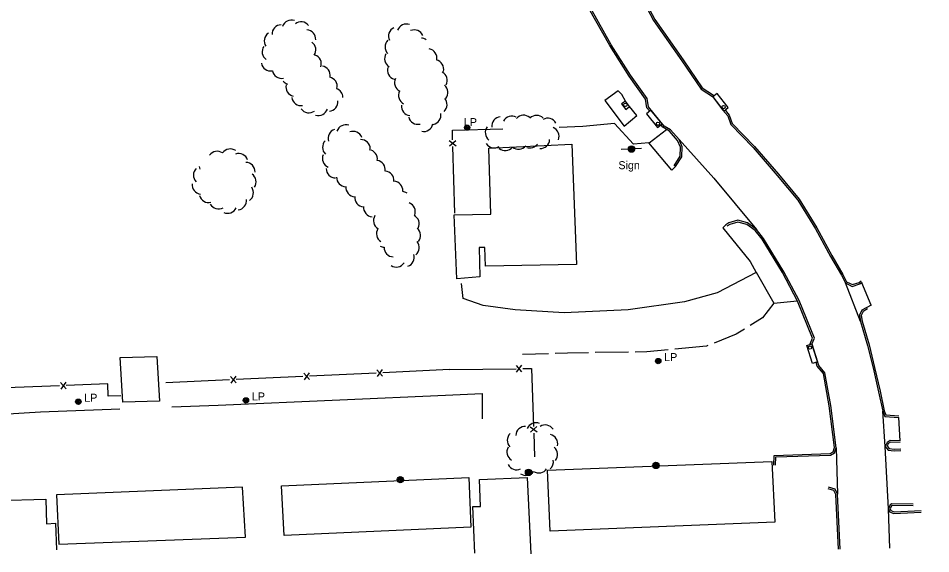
# Model space of a CAD drawing. Extents: x 2402803 to 2427059, y 6985292 to 6997652.
# Drawn here: x 2406106 to 2406653, y 6990711 to 6991032 of the extents above; entities that cross this region are included whole.
import ezdxf

# ---------------------------------------------------------------- set-up
doc = ezdxf.new("R2010")
doc.units = 0
for name, color, linetype in [('p_drainage conc drain', 7, 'Continuous'), ('p_dtm sidewalk', 7, 'Continuous'), ('p_road - paved curb', 7, 'Continuous'), ('p_road bridge end', 7, 'Continuous'), ('p_road dirt road', 7, 'Continuous'), ('p_structure building', 7, 'Continuous'), ('p_structure fence', 7, 'Continuous'), ('p_structure general', 7, 'Continuous'), ('p_structure sign', 7, 'Continuous'), ('p_utility manhole', 7, 'Continuous'), ('p_veg woods', 7, 'Continuous')]:
    doc.layers.add(name, color=color, linetype=linetype)

msp = doc.modelspace()

# ---------------------------------------------------------------- linework, layer by layer
at = {"layer": 'p_drainage conc drain'}
msp.add_lwpolyline([(2406470.12, 6990982.64), (2406467.75, 6990986.64), (2406465.58, 6990988.81), (2406457.6, 6990982.96), (2406469.2, 6990967.61), (2406476.89, 6990973.94), (2406472.53, 6990979.37)], dxfattribs=at)
at = {"layer": 'p_dtm sidewalk'}
for points in [[(2406484.14, 6990957.47), (2406494.7, 6990965.58)], [(2406548.34, 6990880), (2406559.06, 6990861.41), (2406573.07, 6990862.77)]]:
    msp.add_lwpolyline(points, dxfattribs=at)
at = {"layer": 'p_road - paved curb'}
for points in [[(2406708.9, 6991166.9), (2406647.83, 6991166.44), (2406582.25, 6991166.09), (2406531.73, 6991165.73), (2406487.36, 6991165.29), (2406459.5, 6991165.37), (2406452.36, 6991163.12), (2406447.05, 6991158.65), (2406443.39, 6991153.84), (2406440.89, 6991146.51), (2406441.68, 6991141.43), (2406444.32, 6991132.11), (2406449.65, 6991114.89), (2406456.34, 6991094.62), (2406466.16, 6991073.25), (2406480.07, 6991045.94), (2406487.68, 6991031.47), (2406504.65, 6991007.34), (2406516.03, 6990990.53), (2406522.84, 6990986.1), (2406523.08, 6990985.78)], [(2406484.48, 6990976.73), (2406482.92, 6990978.65), (2406482, 6990983.74), (2406472.17, 6990997.55), (2406460.68, 6991015.91), (2406448.13, 6991038.09), (2406436.79, 6991060.23), (2406427.45, 6991082.91), (2406418.15, 6991108.07), (2406409.15, 6991138.19), (2406403.36, 6991163.29)], [(2406500.1, 6990943.3), (2406503.79, 6990949.22), (2406504.04, 6990955.11), (2406502.14, 6990959.6), (2406497.11, 6990965.32), (2406493.14, 6990967.66), (2406483.86, 6990979.08), (2406482.94, 6990984.14), (2406473, 6990998.11), (2406461.54, 6991016.42), (2406449.01, 6991038.56), (2406437.7, 6991060.65), (2406428.38, 6991083.27), (2406419.1, 6991108.39), (2406410.12, 6991138.45), (2406404.33, 6991163.52)], [(2406479.18, 6991045.48), (2406486.82, 6991030.95), (2406503.83, 6991006.77), (2406515.32, 6990989.8), (2406522.15, 6990985.35), (2406528.43, 6990977.21), (2406531.41, 6990973.69), (2406533.13, 6990968.64), (2406546.64, 6990954.69), (2406561.01, 6990938.03), (2406573.31, 6990923.17), (2406583.97, 6990906.08), (2406592.97, 6990889.44), (2406599.51, 6990878.21), (2406601.92, 6990873.54), (2406606.04, 6990871.43), (2406610.59, 6990872.99), (2406611.99, 6990873.96)], [(2406529.95, 6990976.96), (2406532.3, 6990974.19), (2406534, 6990969.17), (2406547.38, 6990955.36), (2406561.77, 6990938.68), (2406574.12, 6990923.76), (2406584.83, 6990906.58), (2406593.84, 6990889.93), (2406600.39, 6990878.69), (2406602.66, 6990874.28), (2406606.12, 6990872.51), (2406610.13, 6990873.89), (2406611.42, 6990874.78)], [(2406500.1, 6990943.3), (2406497.91, 6990941.18), (2406484.09, 6990957.53), (2406474.87, 6990956.79), (2406463.52, 6990969.26), (2406444.5, 6990967.33), (2406430.32, 6990966.76)], [(2406499.25, 6990943.83), (2406502.8, 6990949.53), (2406503.03, 6990954.93), (2406501.28, 6990959.06), (2406496.46, 6990964.54), (2406492.48, 6990966.89), (2406491.49, 6990968.11)], [(2406502.14, 6990959.6), (2406523.11, 6990936.3), (2406548.54, 6990905.67)], [(2406530.29, 6990908.38), (2406528.41, 6990906.65), (2406544.8, 6990886.3), (2406548.48, 6990879.75), (2406524.95, 6990867.65), (2406505.5, 6990862.2), (2406471.68, 6990857.46), (2406433.28, 6990855.59), (2406403.89, 6990857.36), (2406384.73, 6990859.94), (2406372.64, 6990864.11), (2406371.67, 6990873.14)], [(2406559.94, 6990764.15), (2406560.17, 6990769.16), (2406592.95, 6990770.32), (2406595.31, 6990771.62), (2406596.41, 6990774.67), (2406593.12, 6990799.94), (2406589.64, 6990819.7), (2406585.95, 6990824.07), (2406581.8, 6990836.88), (2406583.32, 6990840.5), (2406574.11, 6990862.95), (2406564.99, 6990880.21), (2406552.87, 6990900.27), (2406548.54, 6990905.67), (2406543.18, 6990909.56), (2406537.49, 6990911.09), (2406532.09, 6990909.54), (2406530.29, 6990908.32)], [(2406580.81, 6990836.68), (2406580.73, 6990836.92), (2406582.24, 6990840.5), (2406573.2, 6990862.53), (2406564.12, 6990879.72), (2406552.05, 6990899.7), (2406547.84, 6990904.94), (2406542.74, 6990908.64), (2406537.5, 6990910.05), (2406532.52, 6990908.62), (2406530.85, 6990907.49)], [(2406610.95, 6990850.33), (2406601.92, 6990873.54)], [(2406617.32, 6990860.27), (2406611.81, 6990873.59)], [(2406617.25, 6990860.11), (2406617.32, 6990860.27), (2406611.75, 6990857.11), (2406610.41, 6990854.25), (2406610.95, 6990850.33), (2406615.16, 6990836.07), (2406618.49, 6990822.66), (2406621.71, 6990808.32), (2406624.26, 6990796.61), (2406625.54, 6990793.42), (2406633.94, 6990792.82)], [(2406615.2, 6990857.92), (2406615.2, 6990857.92), (2406612.52, 6990856.4), (2406611.44, 6990854.09), (2406611.93, 6990850.54), (2406616.13, 6990836.33), (2406619.46, 6990822.89), (2406622.69, 6990808.54), (2406625.22, 6990796.9), (2406626.24, 6990794.37), (2406634.01, 6990793.82)], [(2406558.94, 6990764.2), (2406559.21, 6990770.13), (2406592.68, 6990771.31), (2406594.5, 6990772.31), (2406595.39, 6990774.78), (2406592.13, 6990799.79), (2406588.7, 6990819.26), (2406585.06, 6990823.57), (2406584.33, 6990825.81)], [(2406197.99, 6990799.16), (2406225.71, 6990800.19), (2406298.7, 6990803.41), (2406362.04, 6990806.24), (2406384.05, 6990807.17), (2406384.08, 6990791.97)], [(2406043.13, 6990760.46), (2406043.42, 6990781.32), (2406042.97, 6990792.02), (2406063.66, 6990792.89), (2406119.32, 6990796.14), (2406166.75, 6990797.99)], [(2406628.57, 6990714.5), (2406627.67, 6990738.01), (2406625.81, 6990775.48), (2406624.26, 6990796.61)], [(2406634.8, 6990778.91), (2406633.94, 6990792.82)], [(2406634.8, 6990778.91), (2406628.72, 6990778.99), (2406626.86, 6990777.91), (2406625.81, 6990775.48), (2406627.56, 6990773.31), (2406631.11, 6990772.93), (2406635.24, 6990773.07)], [(2406634.79, 6990777.91), (2406628.98, 6990777.99), (2406627.65, 6990777.21), (2406626.97, 6990775.64), (2406628.08, 6990774.26), (2406631.15, 6990773.93), (2406635.21, 6990774.07)], [(2406596.41, 6990774.67), (2406597.26, 6990746.95)], [(2406597.69, 6990713.83), (2406596.27, 6990746.67), (2406595.01, 6990748.96), (2406591.48, 6990750.11)], [(2406598.69, 6990713.87), (2406597.26, 6990746.95), (2406595.69, 6990749.79), (2406591.79, 6990751.06)], [(2406642.61, 6990740.84), (2406629.83, 6990741.14), (2406628.75, 6990740.44), (2406627.67, 6990738.01), (2406628.41, 6990736.23), (2406631, 6990735.31), (2406647.39, 6990736)], [(2406642.59, 6990739.84), (2406630.11, 6990740.13), (2406629.54, 6990739.76), (2406628.76, 6990738), (2406629.16, 6990737.02), (2406631.15, 6990736.32), (2406647.35, 6990737)]]:
    msp.add_lwpolyline(points, dxfattribs=at)
at = {"layer": 'p_road bridge end'}
for points in [[(2406522.42, 6990985.16), (2406529.06, 6990976.64), (2406531.65, 6990978.66), (2406525.01, 6990987.18)], [(2406472.53, 6990979.37), (2406470.12, 6990982.64), (2406467.74, 6990980.88), (2406470.15, 6990977.61)], [(2406491.93, 6990968.98), (2406485.3, 6990977.16), (2406482.68, 6990975.04), (2406489.31, 6990966.86)], [(2406581.71, 6990836.94), (2406585.16, 6990826.17), (2406582.21, 6990825.22), (2406578.76, 6990835.99)]]:
    msp.add_lwpolyline(points, close=True, dxfattribs=at)
at = {"layer": 'p_road dirt road'}
for p, q in [((2406423.77, 6990831.1), (2406408.2, 6990830.59)), ((2406471.75, 6990832.03), (2406451.76, 6990831.72))]:
    msp.add_line(p, q, dxfattribs=at)
for points in [[(2406559.06, 6990861.41), (2406552.17, 6990852.54), (2406544.72, 6990847.92)], [(2406541.32, 6990845.82), (2406536.36, 6990842.74), (2406523.22, 6990837.48)], [(2406519.51, 6990835.99), (2406518.66, 6990835.65), (2406499.67, 6990833.82)], [(2406447.76, 6990831.66), (2406435.2, 6990831.47), (2406427.77, 6990831.23)], [(2406495.69, 6990833.43), (2406482.92, 6990832.2), (2406475.75, 6990832.09)]]:
    msp.add_lwpolyline(points, dxfattribs=at)
at = {"layer": 'p_structure building'}
for points in [[(2406368.82, 6990876.07), (2406367.28, 6990914.42), (2406389.27, 6990914.83), (2406388.06, 6990954.38), (2406437.89, 6990956.71), (2406440.58, 6990884.59), (2406386.15, 6990883.5), (2406385.77, 6990894.83), (2406382.28, 6990894.75), (2406382.73, 6990877.11)], [(2406167.05, 6990828.73), (2406189.03, 6990829.34), (2406190.64, 6990802.68), (2406168.5, 6990802.04)], [(2406423.22, 6990761.18), (2406557.82, 6990766.48), (2406559.61, 6990729.97), (2406424.84, 6990724.7)], [(2406377.24, 6990727), (2406265.28, 6990722.11), (2406263.78, 6990751.9), (2406376.01, 6990756.82)], [(2406240.42, 6990751.15), (2406128.78, 6990746.37), (2406130.14, 6990716.87), (2406242.07, 6990721.15)]]:
    msp.add_lwpolyline(points, close=True, dxfattribs=at)
for points in [[(2406379.73, 6990711.39), (2406378.53, 6990739.43), (2406383.01, 6990739.47), (2406382.44, 6990755.59), (2406411.03, 6990756.77), (2406413.33, 6990711.12)], [(2406094.55, 6990713.36), (2406093.27, 6990743.04), (2406122.39, 6990743.76), (2406122.74, 6990729.06), (2406128.23, 6990729.42), (2406128.78, 6990713.45)]]:
    msp.add_lwpolyline(points, dxfattribs=at)
at = {"layer": 'p_structure fence'}
for p, q in [((2406368.46, 6990955.6), (2406364.37, 6990958.68)), ((2406368.37, 6990958.8), (2406364.46, 6990955.48)), ((2406367.66, 6990915.36), (2406366.5, 6990955.34)), ((2406277.05, 6990819.45), (2406280.44, 6990815.6)), ((2406280.25, 6990819.6), (2406277.24, 6990815.45)), ((2406320.49, 6990819.51), (2406280.54, 6990817.64)), ((2406320.99, 6990821.5), (2406324.38, 6990817.65)), ((2406324.19, 6990821.65), (2406321.18, 6990817.51)), ((2406364.43, 6990821.56), (2406324.48, 6990819.69)), ((2406364.43, 6990821.56), (2406404.43, 6990822.09)), ((2406407.85, 6990820.16), (2406404.6, 6990824.12)), ((2406404.65, 6990820.12), (2406407.8, 6990824.16)), ((2406131.23, 6990813.91), (2406134.59, 6990810.04)), ((2406134.43, 6990814.04), (2406131.4, 6990809.91)), ((2406232.61, 6990815.4), (2406194.43, 6990813.61)), ((2406233.11, 6990817.39), (2406236.5, 6990813.54)), ((2406236.31, 6990817.54), (2406233.3, 6990813.4)), ((2406276.55, 6990817.45), (2406236.6, 6990815.58)), ((2406130.71, 6990811.91), (2406090.75, 6990810.24)), ((2406412.91, 6990787.22), (2406417.02, 6990784.16)), ((2406413.02, 6990784.02), (2406416.91, 6990787.36)), ((2406415.01, 6990783.49), (2406415.5, 6990769.19))]:
    msp.add_line(p, q, dxfattribs=at)
for points in [[(2406366.38, 6990959.34), (2406366.21, 6990965.2), (2406396.57, 6990965.91)], [(2406408.43, 6990822.14), (2406413.68, 6990822.21), (2406414.87, 6990787.49)], [(2406167.39, 6990805.78), (2406159.86, 6990805.6), (2406159.62, 6990813.12), (2406134.71, 6990812.08)]]:
    msp.add_lwpolyline(points, dxfattribs=at)
at = {"layer": 'p_structure general'}
for centre in [(2406469.97, 6990980.36), (2406528.86, 6990979.03), (2406489.49, 6990969.04), (2406580.6, 6990834.76)]:
    msp.add_circle(centre, 1, dxfattribs=at)
at = {"layer": 'p_structure sign'}
msp.add_line((2406479.68, 6990954.09), (2406467.52, 6990953.53), dxfattribs=at)
for radius in [1.9, 1.44, 0.973, 0.539, 0.192]:
    msp.add_circle((2406473.6, 6990953.81), radius, dxfattribs=at)
at = {"layer": 'p_utility manhole'}
for centre, radius in [((2406375.1, 6990966.68), 1.6), ((2406375.1, 6990966.68), 1.3), ((2406375.1, 6990966.68), 1), ((2406375.1, 6990966.68), 0.539), ((2406375.1, 6990966.68), 0.192), ((2406489.66, 6990826.66), 1.6), ((2406489.66, 6990826.66), 1.3), ((2406489.66, 6990826.66), 1), ((2406489.66, 6990826.66), 0.539), ((2406489.66, 6990826.66), 0.192), ((2406141.91, 6990802.3), 1.6), ((2406141.91, 6990802.3), 1.3), ((2406141.91, 6990802.3), 1), ((2406141.91, 6990802.3), 0.539), ((2406242.45, 6990803.07), 1.6), ((2406242.45, 6990803.07), 1.3), ((2406242.45, 6990803.07), 1), ((2406242.45, 6990803.07), 0.539), ((2406242.45, 6990803.07), 0.192), ((2406141.91, 6990802.3), 0.192), ((2406488.3, 6990764.07), 1.9), ((2406488.3, 6990764.07), 1.44), ((2406488.3, 6990764.07), 0.973), ((2406488.3, 6990764.07), 0.539), ((2406411.88, 6990759.9), 1.9), ((2406411.88, 6990759.9), 1.44), ((2406411.88, 6990759.9), 0.973), ((2406411.88, 6990759.9), 0.539), ((2406411.88, 6990759.9), 0.192), ((2406488.3, 6990764.07), 0.192), ((2406335, 6990755.56), 1.9), ((2406335, 6990755.56), 1.44), ((2406335, 6990755.56), 0.973), ((2406335, 6990755.56), 0.539), ((2406335, 6990755.56), 0.192)]:
    msp.add_circle(centre, radius, dxfattribs=at)
at = {"layer": 'p_veg woods'}
for centre, start, end in [((2406263.75, 6991022.75), 92.9275, 182.9275), ((2406269.74, 6991025.58), 71.7181, 161.7181), ((2406275.53, 6991024.49), 37.8632, 127.8632), ((2406338.63, 6991023.17), 69.7873, 159.7873), ((2406259.03, 6991018.67), 123.7834, 213.7834), ((2406278.64, 6991019.66), 356.6336, 86.6336), ((2406333.53, 6991021.55), 116.3137, 206.3137), ((2406343.33, 6991019.67), 22.933, 112.933), ((2406278.69, 6991013.37), 324.6466, 54.6466), ((2406331.47, 6991015.11), 134.8159, 224.8159), ((2406347.22, 6991014.77), 54.9677, 85.5989), ((2406257.78, 6991012.21), 145.1318, 235.1318), ((2406331.21, 6991008.02), 148.7222, 238.7222), ((2406351.29, 6991008.41), 348.8301, 78.8301), ((2406281.99, 6991004.88), 341.1261, 71.1261), ((2406355.38, 6991001.71), 346.7021, 76.7021), ((2406257.21, 6991006.36), 190.8325, 280.8325), ((2406263.83, 6991001.87), 190.8325, 280.8325), ((2406287.33, 6990998.01), 350.5347, 80.5347), ((2406332.89, 6991001.21), 163.1975, 253.1975), ((2406357.46, 6990995.09), 331.1979, 61.1979), ((2406269.2, 6990998.06), 218.9245, 249.9638), ((2406291.49, 6990991.4), 347.8542, 77.8542), ((2406337.16, 6990993.71), 154.6059, 244.6059), ((2406272.05, 6990991.04), 166.5044, 256.5044), ((2406294.97, 6990984.65), 1.785, 71.8874), ((2406357.94, 6990987.74), 321.3869, 51.3869), ((2406275.5, 6990985.5), 188.3713, 278.3713), ((2406339.61, 6990985.94), 152.4945, 242.4945), ((2406357.38, 6990980.55), 313.1065, 39.9739), ((2406291.95, 6990982.2), 275.144, 5.144), ((2406341.27, 6990979.53), 174.1171, 264.1171), ((2406280.21, 6990981.21), 215.5556, 305.5556), ((2406285.88, 6990979.52), 252.7176, 342.7176), ((2406345.53, 6990974.33), 193.2828, 283.2828), ((2406353.69, 6990974.18), 280.9096, 10.9096), ((2406395.57, 6990967.63), 97.0692, 187.0692), ((2406401.85, 6990967.95), 61.8546, 151.8546), ((2406409.01, 6990968.45), 49.5684, 139.5684), ((2406416.7, 6990968.36), 45.0016, 135.0016), ((2406302.31, 6990962.74), 70.6478, 160.6478), ((2406348.95, 6990970), 258.4254, 348.4254), ((2406391.6, 6990963.73), 142.3145, 232.3145), ((2406423.43, 6990966.66), 29.6859, 119.6859), ((2406297.36, 6990960.3), 108.796, 198.796), ((2406306.69, 6990958.79), 20.8256, 110.8256), ((2406424.54, 6990961.45), 338.4861, 68.4861), ((2406294, 6990954.86), 136.0057, 226.0057), ((2406311.33, 6990953.86), 1.1531, 91.1531), ((2406391.24, 6990960.17), 213.1435, 303.1435), ((2406412.66, 6990960.12), 251.653, 324.1292), ((2406418.91, 6990959.83), 267.2573, 357.2573), ((2406225.18, 6990946.87), 55.0426, 145.0426), ((2406233.05, 6990948.26), 55.0426, 145.0426), ((2406238.08, 6990945.48), 19.3372, 109.3372), ((2406315.61, 6990947.78), 352.5689, 82.5689), ((2406397.87, 6990958.57), 230.7051, 320.7051), ((2406405.83, 6990959.36), 230.7051, 320.7051), ((2406242.27, 6990940.21), 358.39, 88.39), ((2406293.96, 6990948.21), 156.7249, 246.7249), ((2406320.34, 6990941.39), 351.8851, 81.8851), ((2406216.56, 6990938.17), 134.2679, 224.2679), ((2406220.07, 6990943.94), 184.9863, 202.1814), ((2406296.18, 6990942.13), 180.4189, 270.4189), ((2406325.46, 6990935.05), 353.9647, 83.9647), ((2406242.9, 6990934.16), 326.0195, 56.0195), ((2406302.44, 6990936.89), 178.2964, 268.2964), ((2406330.86, 6990928.96), 356.0298, 86.0298), ((2406215.76, 6990932.47), 174.3184, 264.3184), ((2406241.27, 6990927.65), 305.1396, 35.1396), ((2406307.97, 6990930.91), 176.2376, 266.2376), ((2406220.04, 6990927.4), 194.587, 284.587), ((2406237.1, 6990922.99), 276.6311, 6.6311), ((2406313.29, 6990924.83), 175.0851, 265.0851), ((2406335.56, 6990922.83), 52.3, 81.9942), ((2406225.95, 6990923.58), 209.6462, 299.6462), ((2406231.43, 6990920.95), 245.9205, 335.9205), ((2406318.59, 6990918.84), 175.0346, 265.0346), ((2406338.34, 6990916.25), 339.0186, 69.0186), ((2406324.56, 6990910.9), 147.9492, 237.9492), ((2406340.7, 6990909.01), 333.4332, 63.4332), ((2406326.35, 6990903.1), 147.9492, 237.9492), ((2406341.52, 6990901.97), 320.1615, 50.1615), ((2406340.71, 6990894.76), 309.1686, 39.1686), ((2406325.43, 6990900.64), 244.691, 268.3311), ((2406330.92, 6990894.82), 178.3311, 268.3311), ((2406337.74, 6990888.92), 287.6699, 17.6699), ((2406332.57, 6990888.67), 236.8903, 326.8903), ((2406409.87, 6990781.85), 87.1177, 177.1177), ((2406416.3, 6990784), 67.4796, 157.4796), ((2406421.95, 6990782.72), 33.2841, 123.2841), ((2406404.79, 6990779.19), 134.3032, 224.3032), ((2406423.73, 6990777.15), 346.9519, 76.9519), ((2406404.54, 6990772.2), 149.7407, 239.7407), ((2406423.62, 6990770.63), 321.0848, 51.0848), ((2406404.76, 6990767.13), 205.1926, 295.1926), ((2406421.13, 6990766.18), 312.1774, 10.5659), ((2406410.3, 6990763.74), 234.9377, 324.9377), ((2406418.02, 6990765.23), 236.9373, 326.9373)]:
    msp.add_arc(centre, 5.65, start, end, dxfattribs=at)

# ---------------------------------------------------------------- texts
at = {"layer": 'p_structure sign'}
msp.add_text('Sign', height=4.8, dxfattribs=at).set_placement((2406465.79, 6990941.75))
at = {"layer": 'p_utility manhole'}
for p in [(2406369.53, 6990967.62), (2406489.66, 6990826.66), (2406141.91, 6990802.3), (2406242.45, 6990803.07)]:
    msp.add_text('  LP', height=4.8, dxfattribs=at).set_placement(p)

doc.saveas('drawing.dxf')
